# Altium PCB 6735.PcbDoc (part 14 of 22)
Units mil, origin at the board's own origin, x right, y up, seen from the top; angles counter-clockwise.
Board outline 2641.73 x 5165.35 mil, 6 copper layers (Top, Inner Layer 2, Inner Layer 3, Inner Layer 4, Inner Layer 5, Bottom), stack 35.7 mil thick; 1011 components, 790 nets, 4118 pads, 9325 vias.
Unrouted connection lines stored in the file: 4610.
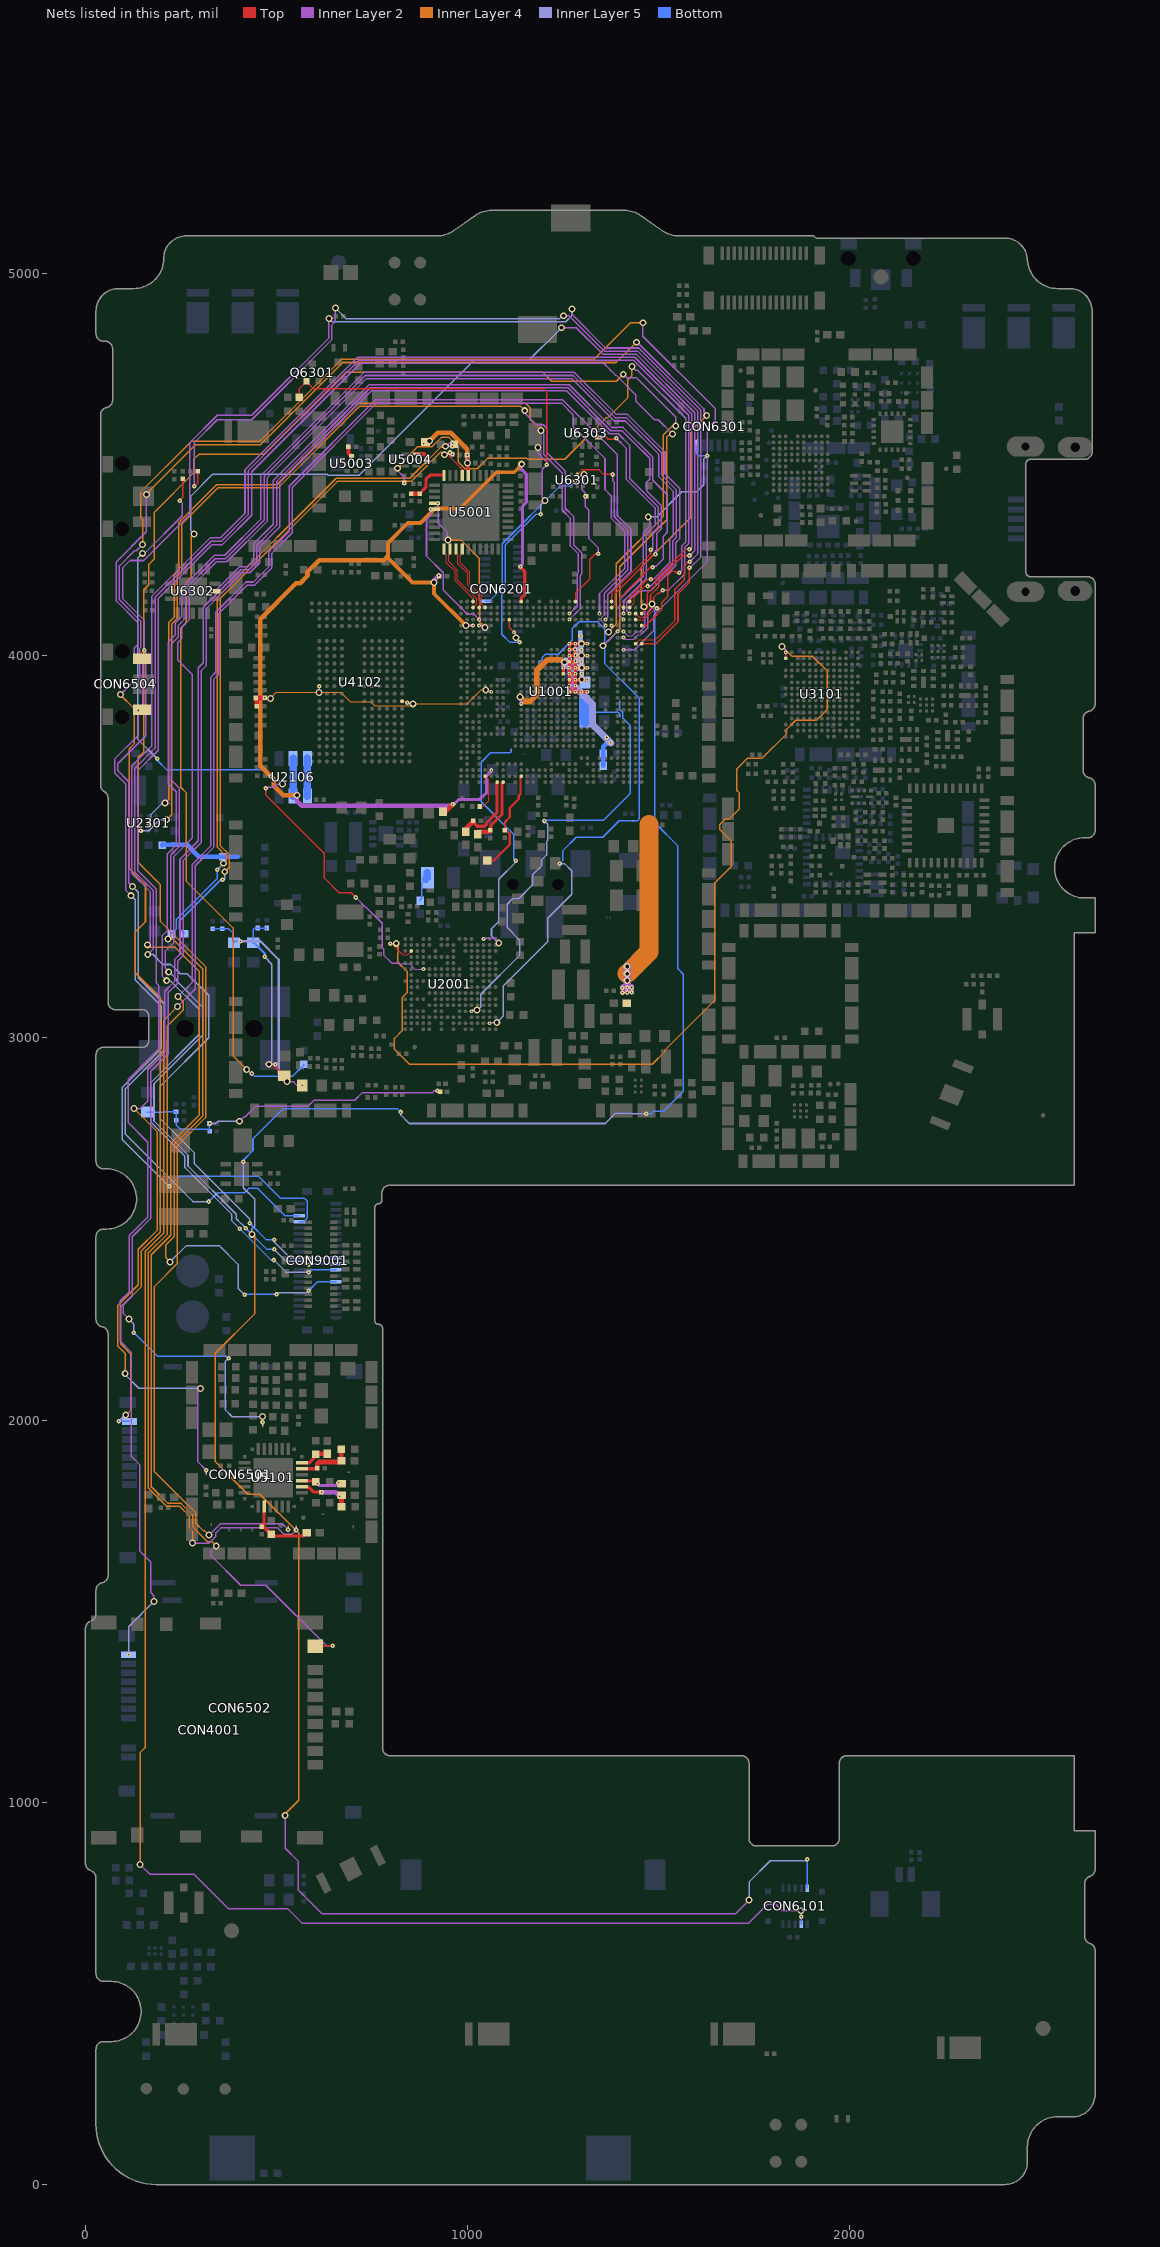
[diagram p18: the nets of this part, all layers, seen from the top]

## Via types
v1: diameter 12, hole 4, Top to Inner Layer 2, 3329 vias
v2: diameter 12, hole 4, Inner Layer 5 to Bottom, 3071 vias
v3: diameter 18, hole 10, Inner Layer 2 to Inner Layer 5, 1928 vias
v4: diameter 10, hole 4, Top to Inner Layer 2, 525 vias
v5: diameter 20, hole 12, Top to Bottom, 472 vias

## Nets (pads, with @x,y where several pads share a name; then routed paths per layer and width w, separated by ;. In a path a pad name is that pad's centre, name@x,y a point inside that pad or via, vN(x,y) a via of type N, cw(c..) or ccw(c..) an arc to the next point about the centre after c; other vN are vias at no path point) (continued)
DVDD18_MSDC0: C10092.1 R1014.1 U1001.C27 U1001.F3 U1001.L31 | length 2756.4
  Top w4: v1(923.95,4209.83) C10092.1@925.95,4207.83 ; U1001.F3@1061.3,3700.59 v4(1061.47,3700.77) 1061.3,3700.76 U1001.F3@1061.3,3700.59
  Top w8: v1(1137.08,4233.11) 1149.31,4220.87 1149.31,4159.09 1140.21,4149.98 U1001.L31@1140.21,4141.71
  Top w12: R1014.1@935.31,3592.09 935.31,3593.09 943.24,3593.09 v1(961.54,3611.4)
  Inner Layer 2 w8: v1(961.54,3611.4) 963.9,3611.15 971.31,3618.57 976.57,3623.83 976.83,3624.09 1031.71,3624.09 1049.8,3642.18 1049.8,3686.34 1061.47,3698.01 v4(1061.47,3700.77) ; v3(995.29,4079.24) 997.95,4078.49 v4(1014.23,4078.72) ; v1(1137.08,4233.11) 1143.31,4239.34 1143.31,4390.93 1153.31,4400.93 1153.31,4475.09 1141.31,4487.09 v3(1141.31,4501.09)
  Inner Layer 2 w12: v3(553.3,3634.73) 553.3,3619.73 565.94,3607.09 957.24,3607.09 v1(961.54,3611.4) ; v3(912.29,4191.35) 912.29,4198.17 v1(923.95,4209.83)
  Inner Layer 4 w10: v3(995.29,4079.24) 912.29,4162.23 v3(912.29,4191.35) 855.63,4191.35 791.31,4255.67 791.31,4260.22 791.31,4295.04 843.34,4347.07 876.94,4347.07 914.97,4385.09 980.73,4385.09 1075.43,4479.79 1121.81,4479.79 1142.21,4500.19 v3(1141.31,4501.09)
  Inner Layer 4 w12: v3(553.3,3634.73) 517.9,3634.73 492.96,3659.68 492.96,3676.39 456.81,3712.53 456.81,4095.59 550.75,4189.53 561.52,4189.53 581.01,4209.02 581.01,4219.64 611.46,4250.09 781.18,4250.09 791.31,4260.22
DVDD28_MSDC1: C10091.1 R1016.1 U1001.G1 | length 211.4
  Top w8: C10091.1@1013.95,3567.83 C10091.1@1014.95,3567.83 ; C10091.1@1014.95,3565.92 1013.04,3565.92 1025.12,3553.83 1044.26,3553.83 1049.31,3558.88 1049.31,3562.14 1077.22,3590.04 U1001.G1@1077.22,3669.27
  Top w12: R1016.1@995.31,3539.09 995.31,3540.09 993.21,3540.09 993.21,3546.09 1013.04,3565.92 C10091.1@1014.95,3567.83 1014.95,3565.92 C10091.1@1014.95,3564.49
DVDD28_SIM1: C10089.1 R1022.1 U1001.H1 | length 188.4
  Top w8: C10089.1@1058.95,3542.83 1060.31,3542.83 1060.31,3552.87 1061.31,3553.87 1061.31,3557.02 1090.31,3586.02 1090.31,3666.61 U1001.H1@1092.97,3669.27
  Top w12: R1022.1@1025.95,3532.49 R1022.1@1025.95,3533.49 ; R1022.1@1029.95,3537.49 R1022.1@1025.95,3533.49 ; C10089.1@1058.95,3542.83 1055.61,3539.49 1025.95,3539.49 R1022.1@1025.95,3533.49
DVDD28_SIM2: C10088.1 R1023.1 U1001.L2 | length 282.6
  Top w6: R1023.1@1051.31,3464.09 1068.09,3464.09 1109.95,3505.95 1109.95,3533.31 1098.19,3545.07 1098.19,3543.83 C10088.1@1097.56,3543.83 ; C10088.1@1096.95,3543.83 C10088.1@1097.56,3543.83 ; U1001.L2@1140.21,3685.02 1137.95,3685.01 1137.95,3638.49 1133.95,3634.49 1133.95,3625.49 1109.95,3601.49 1109.95,3577.49 1097.56,3565.1 C10088.1@1097.56,3543.83
DVDD_EPMU1: C5123.1 R5128.1 SH5102.2 U5101.14 | length 161.6
  Top w4: 668.95,1905.47 669.95,1904.47 SH5102.2@669.95,1893.49
  Top w10: U5101.14@566.2,1872.71 606.3,1872.71 C5123.1@606.3,1874.09
  Top w12: C5123.1@606.3,1874.09 606.3,1886.09 610.7,1890.49 665.95,1890.49 668.95,1893.49 668.95,1905.47 R5128.1@668.95,1923.49
DVDD_EPMU2: C5125.1 R5129.1 SH5105.2 U5101.11 | length 144.6
  Top w4: C5125.1@616.95,1811.49 v1(617.95,1811.49) ; v1(665.31,1801.09) 669.95,1801.09 SH5105.2@670.95,1803.49
  Top w8: U5101.11@566.2,1825.47 583.2,1825.46 596.18,1812.49 616.95,1812.49 C5125.1@616.95,1811.49
  Top w12: R5129.1@669.95,1773.49 SH5105.2@669.95,1801.09
  Inner Layer 2 w12: v1(617.95,1811.49) 654.91,1811.49 v1(665.31,1801.09)
DVDD_IO_NFC: C5121.2 R5116.1 SH5109.2 U5101.3 | length 187.3
  Top w8: C5121.2@460.95,1721.49 467.68,1728.21 U5101.3@467.68,1774.19 ; R5116.1@486.3,1701.09 490.31,1697.08 571.3,1697.08 SH5109.2@579.31,1705.09
  Top w10: C5121.2@460.95,1721.49 465.9,1721.49 R5116.1@486.3,1701.09
DVDD_LTE: C10065.1 C10066.1 C10067.1 C10068.1 C10069.1 C10070.1 C10071.1 C10079.1 C10080.1 R1013.2 SH1004.2 U1001.AA16 U1001.AA18 U1001.AA20 U1001.AA22 U1001.AA24 U1001.AB16 U1001.AB18 U1001.AB20 U1001.AB22 U1001.AB24 U1001.W16 U1001.W17 U1001.W18 U1001.W19 U1001.W20 U1001.W21 U1001.W22 U1001.W23 U1001.W24 U1001.Y16 U1001.Y17 U1001.Y18 U1001.Y19 U1001.Y20 U1001.Y21 U1001.Y22 U1001.Y23 U1001.Y24 | length 1993.7
  Top w4: R1013.2@1416.31,3091.09 1417.31,3091.09 1420.31,3088.09 R1013.2@1421.31,3088.09 ; R1013.2@1417.31,3095.09 R1013.2@1419.54,3096.51
  Top w8: v4(1313.44,3905.49) v4(1297.69,3905.49) v4(1281.94,3905.49) ; v4(1313.44,3936.99) U1001.AA18@1297.69,3936.99 v4(1281.94,3936.99) ; v4(1313.44,3999.98) U1001.AA22@1297.69,3999.98 ; v4(1313.44,4031.47) U1001.AA24@1297.69,4031.47 v4(1281.94,4031.47) ; U1001.W18@1266.2,3936.99 v4(1266.2,3921.24) U1001.W16@1266.2,3905.49 v4(1281.94,3905.49) ; U1001.W18@1266.2,3936.99 v4(1266.2,3952.73) ; U1001.W18@1266.2,3936.99 v4(1281.94,3936.99) ; v4(1266.2,3952.73) v4(1281.94,3952.73) ; v4(1266.2,3952.73) v4(1266.2,3968.48) ; v4(1266.2,3968.48) v4(1281.94,3968.48) ; v4(1266.2,3968.48) U1001.W21@1266.2,3984.23 ; U1001.W21@1266.2,3984.23 v4(1266.2,3999.98) ; U1001.W21@1266.2,3984.23 v4(1266.2,3999.98) ; U1001.W21@1266.2,3984.23 v4(1281.94,3984.23) ; U1001.W21@1266.2,3984.23 v4(1266.2,3999.98) ; U1001.W21@1266.2,3984.23 v4(1281.94,3984.23) ; v4(1266.2,3999.98) v4(1266.2,4015.73) ; v4(1266.2,3999.98) v4(1266.2,4015.73) ; v4(1266.2,3999.98) v4(1281.94,3999.98) ; v4(1266.2,4015.73) v4(1281.94,4015.73) ; v4(1266.2,4015.73) v4(1266.2,4031.47) v4(1281.94,4031.47) ; v4(1281.94,3905.49) v4(1281.94,3921.24) v4(1281.94,3936.99) ; v4(1281.94,3936.99) v4(1281.94,3952.73) ; v4(1281.94,3936.99) v4(1281.94,3952.73) ; v4(1281.94,3952.73) v4(1281.94,3968.48) ; v4(1281.94,3968.48) v4(1281.94,3984.23) ; v4(1281.94,3968.48) v4(1281.94,3984.23) ; v4(1281.94,3968.48) v4(1313.44,3968.48) U1001.AA20@1297.69,3968.48 v4(1281.94,3968.48) ; v4(1281.94,3984.23) v4(1281.94,3999.98) ; v4(1281.94,3999.98) v4(1281.94,4015.73) ; v4(1281.94,3999.98) U1001.AA22@1297.69,3999.98 ; v4(1281.94,3999.98) U1001.AA22@1297.69,3999.98 ; v4(1281.94,4015.73) v4(1281.94,4031.47)
  Top w12: R1013.2@1417.31,3091.09 R1013.2@1417.31,3095.09
  Inner Layer 2 w8: v4(1266.2,3952.73) v4@1281.68,3952.73 ; v4(1266.2,3968.48) v4(1281.94,3968.48) ; v4(1281.94,3936.99) v4@1281.28,3936.56 ; v4(1281.94,3952.73) v4@1281.68,3952.73 ; v3(1297.95,4031.49) 1297.69,4031.47 v4(1313.44,4031.47) ; v3(1298.19,4000.37) 1298.19,4000.17 1313.44,4000.17 v4(1313.44,3999.98) ; v3(1298.24,3968.49) v4(1313.44,3968.48) ; v4(1313.44,3936.99) 1313.44,3937.22 1298.32,3937.22 v3(1298.32,3937.47) v3@1297.69,3936.98 ; v4@1281.28,3936.56 1281.29,3937 1281.31,3937.62 v4@1281.68,3952.73 ; v4@1281.28,3936.56 1281.52,3936.57 1281.96,3936.58 v3@1297.69,3936.98 ; v4@1281.68,3952.74 1282.07,3968.48 1282.08,3969.1 1297.69,3968.48 v3@1297.69,3936.98
  Inner Layer 2 w10: v4(1281.94,3905.49) v4(1266.2,3921.24) ; v4(1281.94,3921.24) v4(1266.2,3921.24) ; v4(1281.94,3984.23) v4(1266.2,3968.48) v4(1266.2,3952.73) 1281.31,3937.62 v4(1281.94,3936.99) 1281.52,3936.57 v4(1266.2,3921.24) ; v4(1297.69,3905.49) v4(1313.44,3905.49)
  Inner Layer 2 w12: v1(1404.8,3131.2) v1@1404.94,3132.15 ; v1(1405.01,3118.63) 1405.21,3120.13 1405.28,3120.27 v1@1405.31,3123.09 ; v1(1429.81,3119.17) 1429.47,3119.65 v1@1429.31,3123.09 ; v1@1404.94,3132.15 1405.31,3135.09 1417.24,3135.09 v1(1417.24,3131.81) 1417.31,3135.09 1429.31,3135.09 v1(1429.67,3131.88) 1429.31,3131.88 v1@1429.31,3123.09 ; v1@1404.94,3132.15 1405.31,3132.15 v1@1405.31,3123.09 ; v1@1405.31,3123.09 v1@1429.31,3123.09
  Inner Layer 2 w20: v1@1417.31,3135.09 v3(1417.31,3150.09) v3(1417.31,3168.09) v3(1417.31,3187.09)
  Inner Layer 4 w20: v3(1417.31,3150.09) v3(1417.31,3168.09)
  Inner Layer 4 w50: v3(1417.31,3168.09) 1474.31,3225.09 1474.31,3238.38 1473.95,3238.74 1473.95,3557.67
  Inner Layer 5 w12: v2(1295.31,4052.09) 1295.31,4034.12 v3(1297.95,4031.49) ; v2(1296.95,4015.49) v2@1297.45,4015.49 ; v2@1298.1,3984.49 1298.1,3968.49 v3(1298.24,3968.49) 1298.6,3968.49 v2@1298.6,3952.49 ; v3(1298.32,3937.47) 1298.64,3937.47 1298.64,3952.49 v2(1298.95,3952.49) ; v2@1282.95,4000.49 v2(1282.95,3988.49) 1282.95,3986.49 1296.95,3986.49 v2(1296.95,3984.49) 1298.07,3984.49 v3@1298.07,4000.37 ; v2@1282.95,4000.49 v2(1282.95,4002.49) ; v2@1282.95,4000.49 v3@1297.57,4000.49 ; v2(1282.95,4002.49) 1282.95,4014.27 v2(1280.79,4016.42) v2@1297.45,4016.42 ; v2(1282.95,4002.49) v3@1297.57,4002.49 ; v2@1297.45,4015.49 1297.57,4015.49 v3@1297.57,4002.49 ; v2@1297.45,4015.49 v2@1297.45,4016.42 ; v2@1297.45,4016.42 v3@1297.45,4026.09 ; v3@1297.45,4026.09 1297.95,4026.09 v3(1297.95,4031.49) ; v3@1297.45,4026.09 1297.45,4031.49 v3(1297.95,4031.49) ; v3@1297.57,4000.49 v3@1297.57,4002.49 ; v3@1297.57,4000.49 v3@1298.15,4000.49 ; v3@1297.57,4000.49 v3(1298.19,4000.37) ; v3@1297.57,4000.49 1297.57,4000.37 v3@1298.07,4000.37 ; v3@1297.57,4002.49 v3@1298.16,4000.49 ; v3@1297.57,4002.49 1298.19,4002.49 1298.19,4000.49 v3(1298.19,4000.37) ; v3@1298.07,4000.37 v3(1298.19,4000.37) ; v3@1298.15,4000.49 v3(1298.19,4000.37) ; v3@1298.16,4000.49 v3(1298.19,4000.37)
  Bottom w4: C10069.1@1294.95,4059.49 1295.31,4059.12 v2(1295.31,4052.09) ; C10067.1@1301.31,3828.49 C10067.1@1306.36,3828.49 C10067.1@1306.36,3826.49 ; 1312.9,3852.16 1393.47,3852.16 1397.31,3848.32 SH1004.2@1397.31,3842.09
  Bottom w12: C10071.1@1294.95,4016.49 C10070.1@1294.95,4037.49
  Bottom w30: C10067.1@1306.36,3828.49 C10066.1@1306.36,3879.49
  other v1: 1417.17,3118.83
DVDD_SIM1: C5124.1 SH5101.2 U5101.15 | length 82.7
  Top w8: U5101.15@566.2,1888.46 585.85,1888.46 605.42,1908.02 C5124.1@605.42,1910.49
  Top w12: C5124.1@605.42,1910.49 C5124.1@602.95,1910.49 603.95,1911.49 SH5101.2@632.95,1911.49
DVDD_SIM2: C5126.1 SH5104.2 U5101.12 | length 117.9
  Top w4: C5126.1@602.95,1838.49 v1(607.31,1834.09) ; v1(662.11,1836.06) 670.95,1836.06 SH5104.2@670.95,1833.49
  Top w8: U5101.12@566.2,1841.22 566.2,1841.49 U5101.12@566.2,1841.22 602.95,1841.21 C5126.1@602.95,1838.49
  Inner Layer 2 w8: v1(607.31,1834.09) 612.84,1828.56 654.61,1828.56 v1(662.11,1836.06)
DVDD_SRAM: C10004.1 C10005.1 R1027.1 U1001.L14 U1001.V19 U1001.V20 | length 616.7
  Top w8: U1001.V19@1250.45,3952.73 1250.45,3968.41 v4(1250.45,3968.48)
  Inner Layer 2 w10: v3(1136.82,3891.87) 1140.21,3888.47 v4(1140.21,3873.99)
  Inner Layer 2 w12: v4@1250.45,3968.48 1250.45,3982.83 v3(1252.95,3982.83)
  Inner Layer 4 w15: v3(1136.82,3891.87) 1148.48,3880.2 1163.01,3880.2 1180.95,3898.14 1180.95,3961.84 1208.66,3989.55 1244.56,3989.55 1252.09,3982.02 v3(1252.95,3982.83)
  Inner Layer 5 w4: v2@1373.82,3772.6 1374.31,3773.09 1375.31,3773.09 v2(1374.56,3771.86)
  Inner Layer 5 w18: v3(1252.95,3982.83) 1252.76,3982.68 1277.21,3958.23 1277.21,3923.49 1326.95,3873.75 1326.95,3819.47 1373.82,3772.6 v2(1374.56,3771.86)
  Bottom w4: C10005.1@1374.31,3772.09 v2(1374.56,3771.86)
  Bottom w12: R1027.1@1354.31,3712.09 C10004.1@1354.31,3745.09 1354.31,3761.43 1363.97,3771.09 1374.31,3771.09 1374.05,3771.35 v2(1374.56,3771.86) ; v2(1363.38,3785.95) 1374.31,3775.01 C10005.1@1374.31,3772.09
EINT_ACC: U1001.AH29 U6303.5 | length 584.7
  Top w4: U6303.5@1341.94,4571.65 1362.79,4571.64 1367.95,4566.49 1386.67,4566.49 v1(1388.93,4568.75)
  Inner Layer 2 w4: v1(1388.93,4568.75) 1415.46,4542.22 1415.46,4461.32 1490.31,4386.46 1490.31,4340.4 1467.31,4317.4 1467.31,4202.09 1407.93,4142.71 v4(1407.93,4110.21)
EINT_ALPS: CON6301.1 U1001.AH28 | length 621
  Inner Layer 2 w3: 1402.67,4151.09 1397.42,4145.84 1397.42,4104.97 v4(1407.93,4094.47)
  Inner Layer 2 w4: 1402.67,4151.09 1459.31,4207.73 1459.31,4320.72 1476.31,4337.72 1476.31,4359.28 v3(1472.5,4363.1)
  Inner Layer 5 w4: v3(1472.5,4363.1) 1494.66,4363.1 1560.31,4428.75 1598.84,4428.75 1617.42,4447.33 1617.42,4514.62 1626.34,4523.54 v2(1627.09,4522.8)
  Bottom w4: CON6301.1@1597.87,4550.11 1597.87,4528.95 1604.03,4522.8 v2(1627.09,4522.8)
EINT_CTP: CON6101.9 U1001.AH25 | length 6387
  Top w4: v4(1407.93,4047.22) 1407.93,4047.7 v4(1407.93,4047.22)
  Inner Layer 2 w3: v4(1407.93,4047.22) 1412.04,4043.11 1434.08,4043.11 1445.46,4054.49 1453.23,4054.49 1457.23,4058.49
  Inner Layer 2 w4: v3(522.55,965.62) 522.55,879.86 556.13,846.27 556.13,771.09 618.13,709.09 1701.31,709.09 v3(1736.31,744.09) ; 1457.23,4058.49 1471.31,4072.57 1471.31,4113.67 1481.52,4123.87 1481.52,4134.87 v3(1482.62,4134.87)
  Inner Layer 4 w4: v3(435.31,2486.09) 442.31,2479.09 442.31,2277.83 339.31,2174.83 339.31,1891.56 424.78,1806.09 456.26,1806.09 557.95,1704.4 557.95,1005.35 521.58,968.98 521.58,959.08 v3(522.55,965.62)
  Inner Layer 5 w4: v2(412.95,2676.32) 412.95,2607.95 443.31,2577.59 443.31,2508.09 435.31,2500.09 v3(435.31,2486.09) ; v2(825.31,2806.09) 825.31,2798.09 847.31,2776.09 1360.21,2776.09 1386.95,2802.83 1426.2,2802.83 1427.88,2801.15 v2(1467.12,2801.15) ; v3(1482.62,4134.87) 1483.08,4135.33 1494.82,4123.59 v2(1495.28,4124.05) ; v3(1736.31,744.09) 1736.31,791.49 1791.91,847.09 1887.95,847.09 1887.95,851.39 v2(1888,851.44)
  Bottom w4: v2(412.95,2676.32) 414.15,2681.09 438.31,2705.25 438.31,2736.09 516.31,2814.09 817.31,2814.09 v2(825.31,2806.09) ; v2(1467.12,2801.15) 1478.73,2801.15 1485.15,2807.57 1511.8,2807.57 1564.31,2860.09 1564.31,3166.69 1550,3181 1550,3502.16 1489.31,3562.85 1489.31,4118.08 v2(1495.28,4124.05) ; CON6101.9@1888,775.18 v2(1888,851.44)
EINT_EAR: R6005.2 U1001.AK29 | length 3981.9
  Top w3: U1001.AK29@1439.43,4110.21 1448.84,4100.79 1459.07,4100.79 1478.31,4120.03 1478.31,4143.86
  Top w4: 1478.31,4143.86 1478.31,4158.49 1499.83,4180.01 1499.83,4197.59 1564.33,4262.09 v1(1580.31,4262.09)
  Inner Layer 2 w4: v3(1245.37,4858.16) 1284.31,4858.16 1353.39,4789.09 1440.73,4789.09 1594.31,4635.51 1594.31,4275.12 1580.8,4261.6 v1(1580.31,4262.09)
  Inner Layer 4 w4: v3(283.95,4318.83) 276.63,4311.51 276.63,4205.29 264.31,4192.97 264.31,4087.09 249.31,4072.09 249.31,3655.78 264.31,3640.78 264.31,3409.58 386.31,3287.58 386.31,2953.1 v3(421.82,2917.59)
  Inner Layer 5 w4: v3(283.95,4318.83) 275.95,4326.83 275.95,4418.06 333.03,4475.14 631.31,4475.14 634.36,4472.09 715.92,4472.09 1017.92,4774.09 1161.21,4774.09 1232.95,4845.83 v3(1245.37,4858.16) ; v3(421.82,2917.59) 422.52,2918.29 434.59,2906.22 v2(435.29,2906.92)
  Bottom w4: v2(435.29,2906.92) 442.12,2900.09 542.53,2900.09 570.95,2928.51 R6005.2@570.95,2931.49
EINT_GYRO: U1001.AH30 U6302.7 | length 2028.1
  Top w3: U1001.AH30@1407.93,4125.96 1403.56,4130.33 1399.18,4134.7 1398.31,4135.57 1398.31,4151.81 1405.39,4158.88 1406.11,4158.88 1412.31,4165.09
  Top w4: v1(331.88,4168.49) 331.92,4169.2 331.95,4169.83 338.02,4169.83 U6302.7@339.02,4168.83 ; 1412.31,4165.09 1478.42,4231.2 v1(1483.98,4231.2)
  Inner Layer 2 w4: v1(331.88,4168.49) 338.8,4168.49 403.14,4232.83 422.92,4232.83 439.95,4249.86 439.95,4292.63 491.31,4343.99 491.31,4458.48 741.92,4709.09 1265.6,4709.09 1377.6,4597.09 1392.31,4597.09 1392.59,4597.37 1406.63,4597.37 1484.31,4519.69 1484.31,4459.29 1522.31,4421.29 1522.31,4322.8 1512.31,4312.8 1512.31,4253.42 1493.34,4234.45 1487.23,4234.45 v1(1483.98,4231.2)
EINT_M: U1001.AE27 U6301.C2 | length 548.5
  Top w4: v1(1379.31,4474.18) 1355.69,4474.18 1343.79,4486.09 1298.8,4486.09 U6301.C2@1286.96,4474.24 ; U6301.C2@1286.95,4474.24 1287.45,4474.23 U6301.C2@1286.96,4474.24
  Inner Layer 2 w3: 1357.08,4106.61 1350.81,4100.34 1350.81,4090.44 1361.61,4079.64 v4(1360.69,4078.72)
  Inner Layer 2 w4: 1357.08,4106.61 1357.08,4162.86 1419.31,4225.09 1419.31,4327.72 1383.31,4363.72 1383.31,4454.19 1379.31,4458.19 v1(1379.31,4474.18)
EINT_NFC: SH5112.1 U1001.AE28 | length 4808.5
  Top w4: v1@550.95,1711.49 v1(550.95,1712.49) SH5112.1@550.95,1719.49 ; v4(1360.69,4094.47) 1361.31,4095.09 v4(1360.69,4094.47)
  Inner Layer 2 w4: v3(242.31,3108.09) 279.31,3145.09 279.31,3453.85 327.31,3501.85 327.31,3943.24 340.82,3956.75 340.82,4113.81 419.84,4192.83 439.49,4192.83 479.95,4233.29 479.95,4272.51 532.95,4325.51 532.95,4443.55 758.49,4669.09 1248.91,4669.09 1391.31,4526.68 1391.31,4367.03 1427.31,4331.03 1427.31,4221.09 1366.31,4160.09 1366.31,4100.09 v4(1360.69,4094.47) ; v3(280.31,1678.09) 323.53,1678.09 340.31,1694.88 340.31,1703.75 354.65,1718.09 502.9,1718.09 519.9,1701.09 539.55,1701.09 v1(550.95,1712.49)
  Inner Layer 4 w4: v3(242.31,3108.09) 255.95,3094.45 255.95,3073.36 214.31,3031.72 214.31,2486.91 164.31,2436.91 164.31,1822.5 212.73,1774.09 246.94,1774.09 271.9,1749.13 271.9,1718.09 280.31,1709.68 v3(280.31,1678.09)
EINT_SD: CON4001.12 U1001.AL29 | length 5655.1
  Top w4: CON4001.12@601.19,1408.54 628.45,1408.54 629.01,1409.09 v1@647.91,1409.09 ; v1(646.95,1409.49) 647.51,1409.49 v1@647.91,1409.09 ; v1@649.58,1409.09 v1@647.91,1409.09 ; U1001.AL29@1455.17,4110.21 1470.31,4125.35 1470.31,4163.32 1491.6,4184.61 1491.6,4200.67 1569.02,4278.09 v1(1580.31,4278.09)
  Inner Layer 2 w4: v3(162.21,3243.55) 169.09,3250.42 169.09,3382.8 121.31,3430.58 121.31,3711.72 173.92,3764.32 173.92,4155.9 327.16,4309.15 353.94,4309.15 417.4,4372.6 417.4,4486.4 712.1,4781.09 1437.42,4781.09 1586.31,4632.19 1586.31,4282.09 1582.31,4278.09 v1(1580.31,4278.09) ; v3(342.04,1670.79) 327.31,1656.06 327.31,1647.12 406.34,1568.09 471.97,1568.09 630.57,1409.49 v1(646.95,1409.49)
  Inner Layer 4 w4: v3(162.21,3243.55) 168.67,3237.09 234.27,3237.09 298.31,3173.04 298.31,2799.09 223.31,2724.09 223.31,2483.87 172.31,2432.87 172.31,1825.82 216.04,1782.09 250.25,1782.09 280.31,1752.03 280.31,1720.99 298.31,1702.99 298.31,1702.88 319.86,1681.33 331.5,1681.33 v3(342.04,1670.79)
ENBB_6169: U2001.R3 U3101.N1 U3101.N2 | length 2577.5
  Top w3: v1(797.26,3246.47) 801.89,3246.47 830.33,3218.02 843.17,3218.02 848.23,3223.09 ; 844.97,3219.83 848.23,3223.09 ; U2001.R3@852.59,3227.44 848.23,3223.09
  Top w4: v1@797.11,3246.47 v1(797.26,3246.47) ; U3101.N2@1832.16,3993.08 v4(1832.16,4008.83)
  Inner Layer 2 w4: v1(797.26,3246.47) 798.32,3245.4 798.39,3245.47 810.94,3245.47 812.96,3247.5 v3(813.25,3247.5) ; v3(1822.65,4024.29) 1823.18,4024.81 1832.16,4015.83 v4(1832.16,4008.83)
  Inner Layer 4 w4: v3(813.25,3247.5) 818.31,3242.44 818.31,3222.14 817.31,3221.14 817.31,3197.96 841.31,3173.96 841.31,3118.09 828.31,3105.09 828.31,3018.68 808.31,2998.68 808.31,2970.25 847.47,2931.09 1482.79,2931.09 1516.31,2964.62 1516.31,2968.27 1645.95,3097.91 ; 1645.95,3097.06 1645.95,3097.91 ; v3(1822.65,4024.29) 1848.29,3998.65 1901.69,3998.65 1940.65,3959.69 1940.65,3891.44 1940.79,3891.3 1940.79,3878.88 1940.65,3878.74 1940.65,3873.04 1941.11,3872.58 1941.11,3860.16 1940.65,3859.7 1940.65,3859.38 1912.32,3831.04 1858.58,3831.04 1834.13,3806.6 1834.13,3795.28 1770.95,3732.1 1732.88,3732.1 1704.06,3703.28 1704.06,3647.74 1711.08,3640.73 1711.08,3599.83 1682.78,3571.54 1672.88,3571.54 1659.65,3558.31 1659.65,3545.26 1689.05,3515.86 1689.05,3447.54 1645.95,3404.44 1645.95,3097.91
EVREF: C4115.1 C4116.1 R1103.1 U1001.F16 U4102.M2 U4102.P13 | length 729.9
  Top w3: U4102.P13@828.35,3880.9 838.29,3880.89 v1(842.08,3877.11)
  Top w12: C4116.1@445.31,3889.39 C4116.1@449.09,3889.39 ; R1103.1@447.95,3867.49 447.95,3888.25 C4116.1@449.09,3889.39 ; C4115.1@468.95,3889.49 468.85,3889.39 C4116.1@449.09,3889.39
  Inner Layer 2 w3: v3(611.08,3904.11) 611.08,3920.26 v1(611.81,3920.26) ; v1(842.08,3877.11) 854.08,3877.11 v3(857.08,3874.11) ; v3(1047.3,3910.55) 1052.37,3905.48 v4(1061.47,3905.49)
  Inner Layer 2 w4: v1(468.81,3890.33) 468.81,3889.33 483.81,3889.33 v3(483.81,3888.33)
  Inner Layer 4 w3: v3(483.81,3888.33) 499.59,3904.11 v3(611.08,3904.11) 667.73,3904.11 692.78,3879.06 746.13,3879.06 756.61,3868.58 851.55,3868.58 v3(857.08,3874.11) 998.81,3874.11 1035.26,3910.55 v3(1047.3,3910.55)
EXTDN: R1101.1 U1001.E2 | length 100.1
  Top w3: R1101.1@1032.89,3604.55 1031.95,3604.55 R1101.1@1031.95,3605.49 1040.59,3605.49 1055.3,3620.2 1055.3,3675.44 U1001.E2@1045.72,3685.02
F2W_CLK: U1001.D28 U5001.5 | length 386
  Top w4: U5001.5@903.17,4382.98 U5001.5@908.95,4382.98 ; v1(903.31,4383.14) 908.79,4383.14 U5001.5@908.95,4382.98 ; U5001.5@923.08,4383.11 U5001.5@913.14,4383.11 ; U5001.5@908.95,4382.98 U5001.5@913.02,4382.98 ; U5001.5@913.02,4382.98 U5001.5@913.14,4383.11 ; U5001.5@913.02,4382.98 U5001.5@913.14,4383.11
  Inner Layer 2 w4: v1(903.31,4383.14) 903.31,4366.92 892.31,4355.92 892.31,4260.83 935.95,4217.19 935.95,4171.67 998.79,4108.83 1015.61,4108.83 v4(1029.98,4094.47)
F2W_DATA: U1001.D27 U5001.4 | length 423.2
  Top w4: U5001.4@913.02,4398.73 921.31,4398.73 v1(921.31,4399.09)
  Inner Layer 2 w4: v1@921.06,4398.83 v1(921.31,4399.09) 923.31,4397.09 923.31,4346.24 947.12,4322.43 947.12,4302.55 v3(948.15,4302.55) ; v4(1029.98,4078.72) 1040.69,4078.71 v3(1045.31,4074.09)
  Inner Layer 4 w4: v3(948.15,4302.55) 982.23,4302.55 1030.31,4254.46 1030.31,4144.77 1031.31,4143.77 1031.31,4088.09 v3(1045.31,4074.09)
FLASH_1: C2323.1 LED2302.1 R2320.2 | length 212.2
  Bottom w12: R2320.2@200.95,3503.49 R2320.2@200.95,3504.49 200.95,3505.49 C2323.1@229.95,3505.49 265.87,3505.49 296.88,3474.48 LED2302.1@358.89,3473.5 398.3,3474.48
FM_ANT: L5002.1 L6001.2 R5013.1 | length 1762.7
  Top w4: v1(961.44,4555.73) 962.9,4552.12 963.31,4551.09 L5002.1@965.31,4553.09
  Inner Layer 2 w4: v3(941.89,4547.87) 942.36,4547.4 951.05,4556.09 961.08,4556.09 v1(961.44,4555.73)
  Inner Layer 4 w4: v3(360.95,3456.83) 367.95,3463.83 367.95,3476.28 344.31,3499.92 344.31,4152.54 655.86,4464.09 848.31,4464.09 930.31,4546.09 938.12,4546.09 940.9,4548.87 v3(941.89,4547.87)
  Inner Layer 5 w4: v2(345.26,3439.75) 344.92,3440.1 361.3,3456.48 v3(360.95,3456.83) ; v3(941.89,4547.87) 941.89,4547.69 960.06,4547.69 v2(960.06,4547.5)
  Bottom w4: L6001.2@224.95,3271.49 224.95,3272.49 237.31,3284.85 237.31,3309.55 345.26,3417.5 v2(345.26,3439.75)
FM_AVDD28: BEAD5001.1 C5008.2 U5001.36 | length 268.5
  Top w4: v1(884.87,4555.09) 889.31,4555.09 BEAD5001.1@889.31,4559.09 ; C5008.2@998.31,4525.09 C5008.2@998.31,4524.09 v1(999.31,4525.09)
  Top w8: C5008.2@998.31,4524.09 1001.21,4521.2 U5001.36@1001.21,4471.17 ; U5001.36@1001.21,4471.17 1000.96,4471.17 U5001.36@1001.21,4471.17
  Inner Layer 2 w12: v1(884.87,4555.09) 895.51,4555.09 901.39,4560.97 v3(900.28,4562.09) ; v3(999.31,4504.09) v1(999.31,4525.09)
  Inner Layer 4 w12: v3(900.28,4562.09) 921.28,4583.09 956.17,4583.09 999.31,4539.95 v3(999.31,4504.09)
FM_RX_N_6625: R5006.1 R6012.2 U5001.37 | length 1817.4
  Top w4: v1(953.76,4531.6) 953.76,4519.67 970.88,4502.55 985.46,4487.97 U5001.37@985.46,4471.17
  Inner Layer 2 w4: v3(939.39,4525.91) 939.57,4526.09 948.25,4526.09 v1(953.76,4531.6)
  Inner Layer 4 w4: v3(364.31,3434.83) 375.95,3446.47 375.95,3479.59 352.31,3503.23 352.31,4149.23 659.17,4456.09 852.64,4456.09 928.64,4532.09 939.39,4532.09 v3(939.39,4525.91)
  Inner Layer 5 w4: v2(358.65,3413.9) 364.63,3413.83 364.63,3434.83 v3(364.31,3434.83) ; v3(939.39,4525.91) 939.39,4526.71 960.06,4526.71 v2(960.06,4527.5)
  Bottom w4: R6012.2@258.95,3272.49 245.31,3286.13 245.31,3305.05 354.09,3413.83 358.65,3413.83 v2(358.65,3413.9)
GND_VCORE_FB: SH1005.2 U2001.C1 | length 685.4
  Inner Layer 2 w4: v4(1041.57,3258.94) 1043.71,3261.09 1068.25,3261.09 v3(1081.25,3248.09)
  Inner Layer 5 w4: v3(1081.25,3248.09) 1062.31,3267.03 1062.31,3285.88 1081.31,3304.88 1081.31,3414.83 1125.47,3458.99 v2(1125.47,3463.9)
  Bottom w4: SH1005.2@1113.95,3753.49 1113.95,3748.67 1110.77,3745.49 1059.32,3745.49 1035.31,3721.48 1035.31,3617.71 1120.64,3532.38 1120.64,3468.73 v2(1125.47,3463.9)
GND_VLTE_FB: SH1003.2 U2001.E13 | length 1134.9
  Inner Layer 2 w4: v4(1010.07,3069.96) 1012.62,3072.51 1024.82,3072.51 v3(1024.82,3072.76)
  Inner Layer 5 w4: v3(1024.82,3072.76) 1025.6,3072.51 1034.31,3081.22 1034.31,3114.2 1135.95,3215.84 1135.95,3256.09 1103.31,3288.73 1103.31,3349.93 1117.37,3363.99 1133.4,3363.99 1169.95,3400.55 1169.95,3427.03 1194.33,3451.41 1194.33,3466.57 1206.31,3478.55 1206.31,3513.63 1209.31,3516.63 1209.31,3559.06 v2(1200.77,3567.6)
  Bottom w4: v2(1200.77,3567.6) 1202.31,3570.09 1355.94,3570.09 1425.31,3639.46 1425.31,3817.69 1405.33,3837.67 1405.33,3851.81 1397.31,3859.83 SH1003.2@1397.31,3880.09
GND_VPROC_PMIC_FB: R1037.1 SH1002.1 | length 805.4
  Bottom w4: SH1002.1@1186.31,3973.09 1186.31,3981.09 1195.02,3989.8 1195.02,3995.28 1203.83,4004.09 1237.13,4004.09 1273.31,4040.27 1273.31,4070.21 1292.19,4089.09 1339.74,4089.09 1358.31,4070.52 1358.31,3979.68 1449.31,3888.68 1449.31,3573.09 1444.31,3568.09 R1037.1@1434.31,3568.09
GND_VPROC_PMIC_FB_6328: R1037.2 U2001.B15 | length 788.3
  Inner Layer 2 w4: v4(1057.32,3038.47) 1057.31,3039.27 1076.31,3039.27 v3(1076.31,3040.08)
  Inner Layer 5 w4: v3(1076.31,3040.08) 1093.31,3057.08 1093.31,3136.09 1209.31,3252.09 1209.31,3313.09 1272.31,3376.09 1272.31,3437.09 1253.31,3456.09 v2(1241.31,3456.09)
  Bottom w4: v2(1241.31,3456.09) 1249.31,3464.09 1249.31,3490.16 1284.24,3525.09 1353.31,3525.09 1396.31,3568.09 R1037.2@1430.31,3568.09
GPIO_CAMERA_RESET: CON6201.21 R6211.2 U1001.Y31 | length 854.6
  Top w4: U1001.Y31@1281.94,4141.71 1283.31,4141.71 1283.31,4164.65 1308.75,4190.09 1309.18,4190.09 1318.95,4199.86 1318.95,4251.06 1334.72,4266.83 v1(1341.95,4266.83) ; v1(1307.31,4417.56) 1310.31,4417.56 R6211.2@1310.31,4417.09
  Inner Layer 2 w4: v3(1304.31,4474.09) 1298.31,4474.09 1298.31,4435.09 1307.31,4426.09 v1(1307.31,4417.56) 1307.31,4390.78 1317.31,4380.78 1317.31,4306.52 1341.95,4281.88 v1(1341.95,4266.83)
  Inner Layer 5 w4: v2(1281.31,4457.09) 1298.31,4474.09 v3(1304.31,4474.09)
  Bottom w4: CON6201.21@1046.63,4142.9 1046.63,4141.89 1055.91,4141.89 1090.31,4176.29 1090.31,4292.82 1241.58,4444.09 1268.31,4444.09 v2(1281.31,4457.09)
GPIO_CTP_RSTB: CON6101.8 U1001.AD29 | length 7077.7
  Inner Layer 2 w4: v3(142.95,837.49) 168.66,811.78 283.64,811.78 373.33,722.09 528.38,722.09 566.38,684.09 1735.17,684.09 1784.17,733.09 1805.81,733.09 1822.71,716.19 v3(1872.25,716.19) ; v3(240.95,3081.83) 287.31,3128.19 287.31,3450.49 335.31,3498.49 335.31,3937.86 348.95,3951.5 348.95,4110.63 423.15,4184.83 442.8,4184.83 487.95,4229.98 487.95,4268.48 540.95,4321.48 540.95,4440.24 761.8,4661.09 1245.27,4661.09 1276.31,4630.04 1276.31,4599.25 1359.31,4516.25 1359.31,4434.51 1375.31,4418.51 1375.31,4360.4 1411.31,4324.4 1411.31,4229.09 1344.93,4162.71 v4(1344.94,4110.21)
  Inner Layer 4 w4: v3(142.95,837.49) 142.95,1130.37 156.31,1143.73 156.31,2441 205.31,2490 205.31,3046.19 v3(240.95,3081.83)
  Inner Layer 5 w4: v2(1872.25,700.19) v3(1872.25,716.19)
  Bottom w4: CON6101.8@1872.25,680.7 v2(1872.25,700.19)
GPIO_FLASH_EN: U1001.W28 U2301.C1 | length 2531.4
  Inner Layer 2 w3: v4(1266.2,4094.47) 1280.22,4108.49
  Inner Layer 2 w4: v3(1149.31,4641.09) 1149.31,4635.09 1179.86,4604.54 1197.47,4604.54 1207.19,4594.81 1207.19,4531.62 1255.31,4483.5 1255.31,4385.59 1276.95,4363.95 1276.95,4290.24 1297.89,4269.3 1297.89,4213.62 1294.95,4210.68 1294.95,4123.22 1280.22,4108.49
  Inner Layer 4 w4: v3(212.3,3570.8) 225.31,3583.81 225.31,4082.4 240.31,4097.4 240.31,4206.94 252.31,4218.94 252.31,4345.03 346.37,4439.09 503.68,4439.09 717.68,4653.09 1137.31,4653.09 v3(1149.31,4641.09)
  Inner Layer 5 w4: v2(145.26,3541.82) 165.3,3541.82 194.57,3571.09 212.3,3571.09 v3(212.3,3570.8)
GPIO_FLASH_STROBE: U1001.W29 U2301.B2 | length 2478.7
  Inner Layer 2 w4: v3(1191.54,4589.26) 1191.15,4588.87 1199.07,4580.95 1199.07,4526.39 1247.31,4478.15 1247.31,4380.57 1268.95,4358.93 1268.95,4286.91 1289.89,4265.97 1289.89,4217.81 1286.95,4214.87 1286.95,4130.97 v4(1266.2,4110.21)
  Inner Layer 4 w4: v3(208.31,3614.52) 217.31,3623.52 217.31,4085.96 232.31,4100.96 232.31,4211.26 244.31,4223.26 244.31,4348.34 343.06,4447.09 500.36,4447.09 714.36,4661.09 1150.53,4661.09 1164.31,4647.3 1164.31,4616.48 v3(1191.54,4589.26)
  Inner Layer 5 w4: v2(164.95,3561.49) 171.31,3567.85 171.31,3584.83 201.23,3614.74 208.09,3614.74 v3(208.31,3614.52)
GPIO_GPS_LNA_EN: R5015.2 U1001.AL27 | length 1724.9
  Top w4: R5015.2@834.08,4452.11 834.08,4451.11 834.1,4451.2 v1(834.21,4451.18) ; U1001.AL27@1455.17,4078.72 1466.26,4078.71 1484.31,4096.77 1508.31,4120.77 1508.31,4139.83 1523.31,4154.83 1523.31,4209.76 1534.06,4220.51 1541.57,4220.51 1544.97,4217.11 v1(1553.97,4217.11)
  Inner Layer 2 w4: v3(816.61,4490.49) 816.8,4490.49 816.78,4487.3 815.2,4485.72 834.21,4466.71 v1(834.21,4451.18) ; v3(1429.55,4756.43) 1438.89,4747.09 1444.46,4747.09 1570.31,4621.24 1570.31,4297.3 1560.31,4287.3 1560.31,4223.81 1553.79,4217.29 v1(1553.97,4217.11)
  Inner Layer 4 w4: v3(816.61,4490.49) 816.66,4490.49 816.2,4487.88 823.98,4495.65 823.98,4501.97 868.1,4546.09 906.2,4546.09 931.2,4571.09 951.2,4571.09 975.31,4546.98 975.31,4506.88 993.1,4489.09 1024.79,4489.09 1051.79,4516.09 1154.87,4516.09 1156.87,4514.09 1253.84,4514.09 1361.84,4622.09 1366.02,4622.09 1418.31,4674.39 1418.31,4720.4 1429.55,4731.64 v3(1429.55,4756.43)
GPIO_NFC_ENB: SH5115.1 U1001.AF31 | length 4526.2
  Top w4: SH5115.1@463.31,1986.09 v1(463.31,1994.09) ; U1001.AF31@1376.43,4141.71 1376.43,4164.09 1478.33,4265.99 1478.33,4275.96 v1(1479.44,4277.06)
  Inner Layer 2 w4: v3(113.7,2264.36) 99.31,2278.75 99.31,2302.12 122.31,2325.12 122.31,2479.62 171.31,2528.62 171.31,2912.78 216.12,2957.58 216.12,3118.03 241.31,3143.22 241.31,3200.92 255.31,3214.92 255.31,3464.09 303.31,3512.09 303.31,3961.26 316.42,3974.37 316.42,4123.35 409.9,4216.83 429.55,4216.83 455.95,4243.24 455.95,4284.59 508.29,4336.92 508.29,4452.83 748.55,4693.09 1258.89,4693.09 1371.22,4580.76 1393.89,4580.76 1423.55,4551.1 1423.55,4464.54 1498.31,4389.78 1498.31,4336.03 1483.95,4321.67 1483.95,4277.06 v1(1479.44,4277.06) ; v1(463.31,1994.09) 462.31,1995.09 462.31,2008.09 v3(463.31,2009.09)
  Inner Layer 5 w4: v3(113.7,2264.36) 126.31,2251.75 v2(126.31,2229.09) ; v2(374.5,2161.63) 365.31,2152.45 365.31,2027.56 383.78,2009.09 v3(463.31,2009.09)
  Bottom w4: v2(126.31,2229.09) 188.31,2167.09 368.31,2167.09 v2(374.5,2161.63)
GPIO_NFC_IRQ: SH5113.1 U1001.AF27 | length 5375.7
  Top w4: v1(529.95,1713.49) 530.95,1714.53 SH5113.1@530.95,1719.49
  Inner Layer 2 w4: v3(323.31,1699.09) 333.02,1708.79 353.06,1728.83 514.61,1728.83 v1(529.95,1713.49) ; v3(1368.31,4062.09) 1376.43,4070.2 v4(1376.43,4078.72) ; v3(1407.14,4736.41) 1416.46,4727.09 1441.84,4727.09 1544.27,4624.65 v3(1544.27,4600.81)
  Inner Layer 4 w4: v3(323.31,1699.09) 312.42,1709.98 308.76,1709.98 288.31,1730.43 288.31,1756.89 180.31,1864.89 180.31,2349.55 240.31,2409.55 240.31,2717.45 314.31,2791.45 314.31,3186.57 195.31,3305.57 195.31,3401.97 138.31,3458.97 138.31,3734.26 152.31,3748.26 152.31,4172.64 165.31,4185.64 165.31,4238.52 180.31,4253.52 180.31,4375.08 282.95,4477.72 282.95,4513.04 297,4527.09 467.13,4527.09 681.13,4741.09 1196.86,4741.09 1220.12,4717.83 1388.56,4717.83 v3(1407.14,4736.41) ; v3(1368.31,4062.09) 1388.88,4082.66 1388.88,4240.84 1512.31,4364.27 1512.31,4578.14 1534.98,4600.81 v3(1544.27,4600.81)
GPIO_NFC_RSTB: SH5114.1 U1001.AF30 | length 4657.6
  Top w3: U1001.AF30@1376.43,4125.96 1377.42,4125.96 1385.95,4134.49 1385.95,4160.36 1385.09,4161.21
  Top w4: SH5114.1@316.31,1861.09 v1(316.31,1869.09) ; 1385.09,4161.21 1385.09,4161.32 1489.69,4265.92 v1(1491.44,4265.92)
  Inner Layer 2 w4: v3(127.31,2815.09) 143.31,2815.09 162.55,2834.33 162.55,2916.41 207.73,2961.59 207.73,3122.36 233.01,3147.63 233.01,3204.8 247.31,3219.1 247.31,3467.62 295.31,3515.62 295.31,3968.52 308.29,3981.49 308.29,4126.53 406.59,4224.83 426.23,4224.83 447.95,4246.55 447.95,4288.61 499.95,4340.61 499.95,4455.81 745.23,4701.09 1262.24,4701.09 1374.56,4588.77 1403.92,4588.77 1430.71,4561.98 1476.31,4516.38 1476.31,4461.86 1468.03,4453.58 1468.03,4431.38 1506.31,4393.09 1506.31,4331.62 1494.76,4320.07 1494.76,4277.4 1491.44,4274.08 v1(1491.44,4265.92) ; v3(301,2083.04) 301.31,2083.09 301.81,2082.59 293.31,2074.09 293.31,1892.09 v1(316.31,1869.09)
  Inner Layer 4 w4: v3(103.9,2122.18) 103.9,2174.37 84.31,2193.96 84.31,2300.09 138.31,2354.09 138.31,2447.09 187.52,2496.3 187.52,2754.88 v3(127.31,2815.09)
  Inner Layer 5 w4: v3(103.9,2122.18) 102.06,2120.34 139.31,2083.09 301,2083.09 v3(301,2083.04)
GPS_ANT: R5007.1 U5004.3 | length 42.1
  Top w10: U5004.3@864.86,4527.86 885.58,4527.86 892.95,4520.49 R5007.1@892.95,4509.49
GPS_AVDD18: C5009.2 SH5001.1 U5001.40 | length 118.9
  Top w8: C5009.2@874.08,4424.11 890.71,4440.74 890.71,4461.49 901.71,4472.49 936.9,4472.49 U5001.40@938.22,4471.17
  Top w12: SH5001.1@852.23,4424.26 852.23,4424.11 C5009.2@874.08,4424.11
GPS_RF_LNA: C5004.2 U5003.1 | length 28.3
  Top w10: C5004.2@688.08,4547.11 688.08,4530.11 U5003.1@696.08,4522.11
GPS_RX_IN: U1001.D30 U5001.13 | length 178
  Top w3: U5001.13@969.71,4279.05 969.71,4267.49 974.08,4263.12 974.08,4241.11 1000.08,4215.11 1000.08,4186.26 1029.97,4156.37 U1001.D30@1029.98,4125.96
GPS_RX_IP: U1001.E30 U5001.14 | length 181.7
  Top w3: U5001.14@985.46,4279.05 985.46,4267.49 981.08,4263.11 981.08,4243.11 1006.08,4218.11 1006.08,4188.74 1036.08,4158.74 1036.08,4135.6 U1001.E30@1045.72,4125.96
GPS_RX_QN: U1001.C31 U5001.11 | length 168.8
  Top w3: U5001.11@938.22,4279.05 939.08,4278.18 939.08,4268.11 944.08,4263.11 944.08,4243.49 967.08,4220.49 967.08,4196.4 1014.23,4149.25 U1001.C31@1014.23,4141.71
GPS_RX_QP: U1001.C30 U5001.12 | length 189.1
  Top w3: U5001.12@953.96,4279.05 953.96,4266.49 950.08,4262.6 950.08,4246.49 973.08,4223.49 973.08,4199.11 1023.65,4148.54 1023.65,4135.38 U1001.C30@1014.23,4125.96
HOMEKEY: R6508.1 U2001.N6 | length 1920.6
  Top w4: v1(246.95,4405.83) 246.95,4406.68 254.36,4414.09 254.36,4434.04 254.31,4434.09 R6508.1@254.31,4463.09 ; v1(471.8,3653.09) 471.8,3635.41 625.31,3481.9 625.31,3418.09 663.57,3379.83 695.22,3379.83 v1(707.68,3367.37)
  Inner Layer 2 w3: 821.31,3195.09 822.31,3194.09 847.83,3194.09 861.83,3180.09 877.31,3180.09 877.42,3180.2 v4(884.09,3180.2)
  Inner Layer 2 w4: v3(149.31,4267.83) 149.31,4268.83 155.95,4268.83 253.31,4366.19 253.31,4399.47 v1(246.95,4405.83) ; v1(471.8,3653.09) 474.8,3656.09 494.98,3656.09 502.8,3663.91 v3(515.6,3663.91) ; v1(707.68,3367.37) 732.96,3342.09 734.28,3342.09 776.31,3300.06 776.31,3236.78 780,3233.09 780,3217.03 801.94,3195.09 821.31,3195.09
  Inner Layer 5 w4: v3(149.31,4267.83) 136.31,4254.83 136.31,3781.88 v2(187.8,3730.39) ; v2(485.31,3685.09) 497.05,3673.35 506.15,3673.35 v3(515.6,3663.91)
  Bottom w4: v2(187.8,3730.39) 187.8,3726.29 213,3701.09 469.31,3701.09 v2(485.31,3685.09)
HP_MIC: BEAD6001.1 C6020.1 C6021.2 R6011.1 R6028.2 R6030.2 | length 868.8
  Top w4: v1(920.95,2861.49) 926.95,2861.49 926.95,2859.49 R6028.2@927.95,2859.49
  Inner Layer 2 w4: v3(403.3,2782.09) 414.85,2793.64 417.86,2793.64 445.05,2820.83 581.82,2820.83 598.08,2837.09 704.66,2837.09 724.66,2857.09 908.18,2857.09 912.58,2861.49 v1(920.95,2861.49)
  Inner Layer 5 w4: v2(325.31,2776.09) 341.31,2776.09 347.31,2782.09 v3(403.3,2782.09)
  Bottom w4: BEAD6001.1@161.95,2805.9 206.95,2805.9 206.95,2804.77 208.67,2806.49 C6021.2@236.95,2806.49 237.95,2805.49 C6020.1@237.95,2784.49 237.95,2771.49 247.95,2761.49 318.91,2761.49 R6030.2@324.31,2756.09 ; R6011.1@322.67,2776.43 323.97,2776.43 R6011.1@324.31,2776.09 ; R6030.2@325.31,2756.09 R6030.2@324.31,2756.09 ; v2(325.31,2776.09) R6011.1@324.31,2776.09 ; R6030.2@324.31,2756.09 R6011.1@324.31,2776.09
HP_MP3L: BEAD6002.2 BEAD6003.1 C6008.1 R6006.1 | length 487.2
  Top w6: v1(496.95,2930.83) 496.21,2930.09 496.21,2924.47 519.44,2901.24 BEAD6002.2@519.95,2901.24
  Inner Layer 2 w4: v3(479.98,2931.08) 479.72,2930.83 v1(496.95,2930.83)
  Inner Layer 5 w5: v2(468.95,3211.83) 487.45,3193.33 487.45,2938.56 v3(479.98,2931.08)
  Bottom w4: BEAD6003.1@431.95,3256.08 BEAD6003.1@438.95,3249.08 ; BEAD6003.1@443.95,3244.49 439.36,3249.08 BEAD6003.1@438.95,3249.08 ; C6008.1@473.81,3287.49 R6006.1@451.31,3287.49 443.14,3287.49 438.95,3283.3 BEAD6003.1@438.95,3249.08
  Bottom w6: BEAD6003.1@439.36,3249.08 440.95,3249.08 468.95,3221.08 v2(468.95,3211.83)
HP_MP3R: BEAD6004.2 BEAD6005.1 C6007.1 R6007.1 | length 607.7
  Inner Layer 2 w4: v3(526.95,2885.83) 543.65,2885.83 553.65,2875.83 v1(567.36,2875.83)
  Inner Layer 5 w6: v2(404.95,3253.28) 457.2,3253.28 505.95,3204.53 505.95,2906.83 v3(526.95,2885.83)
  Bottom w4: C6007.1@333.31,3285.65 R6007.1@358.31,3285.65 374.49,3285.65 385.81,3274.32 385.81,3253.28 BEAD6005.1@388.95,3253.28 ; v2(404.95,3253.28) BEAD6005.1@392.95,3253.28 ; BEAD6005.1@388.95,3249.08 BEAD6005.1@388.95,3249.52 ; BEAD6005.1@388.95,3249.08 BEAD6005.1@389.94,3250.12 ; BEAD6005.1@388.95,3249.08 389.99,3250.12 392.95,3253.08 BEAD6005.1@392.95,3253.28 ; BEAD6005.1@388.95,3249.52 BEAD6005.1@388.95,3253.28 ; BEAD6005.1@388.95,3249.52 389.55,3250.12 BEAD6005.1@389.94,3250.12 ; BEAD6005.1@388.95,3253.28 BEAD6005.1@392.95,3253.28 ; BEAD6005.1@389.94,3250.12 BEAD6005.1@392.95,3253.28
INT_SIM1: CON6501.10 U1001.AH26 | length 5098.3
  Inner Layer 2 w3: v4(1407.93,4062.97) 1418.79,4052.11 1430.08,4052.11 1440.46,4062.49 1449.91,4062.49 1460.51,4073.09
  Inner Layer 2 w4: v3(91.31,3898.09) 141.53,3948.3 141.53,3990.91 127.79,4004.65 127.79,4019.93 136.31,4028.45 136.31,4087.73 80.95,4143.09 80.95,4246.09 159.31,4324.45 v3(159.31,4422.09) ; v3(1441.38,4820.1) 1442.53,4821.26 1618.31,4645.48 1618.31,4637.36 1626.09,4629.58 v3(1625.31,4628.8) ; 1460.51,4073.09 1463.31,4075.89 1463.31,4126.09 v3(1461.31,4128.09)
  Inner Layer 4 w4: v3(91.31,3898.09) 127.32,3862.08 127.32,3769.09 114.31,3756.08 114.31,3443.15 157.1,3400.36 157.1,3303.65 130.31,3276.86 130.31,3170.51 195.52,3105.3 195.52,2492.3 146.31,2443.09 146.31,2349.62 92.31,2295.62 92.31,2199.15 118.9,2172.56 118.9,2026.68 v3(105.31,2013.09) ; v3(159.31,4422.09) 170.2,4432.98 170.2,4434.23 288.06,4552.09 458.19,4552.09 673.19,4767.09 1388.36,4767.09 v3(1441.38,4820.1) ; v3(1461.31,4128.09) 1454.31,4135.09 1454.31,4232.13 1584.31,4362.13 1584.31,4587.8 v3(1625.31,4628.8)
  Inner Layer 5 w4: v2(87.31,1997.09) 103.05,2012.83 105.05,2012.83 v3(105.31,2013.09)
  Bottom w4: v2(87.31,1997.09) 115.3,1997.09 CON6501.10@115.3,1996.66
INT_SIM2: CON6502.10 U1001.AG26 | length 5397.6
  Top w4: v4(1392.18,4062.97) 1392.3,4062.97 1392.3,4062.85 v4(1392.18,4062.97)
  Inner Layer 2 w4: v3(178.95,1525.09) 178.95,1540.45 171.31,1548.09 171.31,1628.29 142.51,1657.09 142.51,1882.89 120.31,1905.09 120.31,2177.25 91.31,2206.25 91.31,2312.09 114.31,2335.09 114.31,2483.03 162.86,2531.58 162.86,2727.3 112.31,2777.85 112.31,2892.03 191.35,2971.07 191.35,3137.76 185.24,3143.87 185.24,3389.32 137.31,3437.25 137.31,3699.58 190.31,3752.58 190.31,4149.67 330.47,4289.83 357.26,4289.83 434.95,4367.52 434.95,4481.32 718.73,4765.09 1356.22,4765.09 1371.31,4750 1371.31,4749.32 1386.54,4734.09 1387.87,4734.09 1439.31,4682.65 1439.31,4667.25 1488.95,4617.62 1498.83,4617.62 v3(1536.1,4580.34) ; v3(1354.31,4026.09) 1374.17,4045.94 1375.15,4045.94 v4(1392.18,4062.97)
  Inner Layer 4 w4: v3(1354.31,4026.09) 1397.95,4069.72 1397.95,4232.49 1520.95,4355.49 1520.95,4572.09 1529.2,4580.34 v3(1536.1,4580.34)
  Inner Layer 5 w4: v2(113.31,1386.09) 113.31,1459.45 v3(178.95,1525.09)
  Bottom w4: v2(113.31,1386.09) 113.31,1386.18 CON6502.10@113.14,1386.35 ; CON6502.10@113.14,1386.35 112.41,1387.09 CON6502.10@113.14,1386.35
IR_GPIO: Q6301.1 R6351.2 U1001.J28 | length 1567.8
  Top w4: R6351.2@558.95,4675.99 558.95,4697.62 Q6301.1@578.2,4716.87 ; Q6301.1@578.2,4717.85 Q6301.1@578.2,4716.87 ; U1001.J28@1108.72,4094.47 1108.71,4073.72 v4(1120.95,4061.49) ; v1(1207.33,4499.65) 1207.33,4690.1 1199.48,4697.96 597.11,4697.96 Q6301.1@578.2,4716.87
  Inner Layer 2 w4: v4(1120.95,4061.49) 1126.31,4056.12 v3(1126.31,4047.09) ; v3(1183.88,4545.09) 1183.88,4529.87 1207.33,4506.42 v1(1207.33,4499.65) 1195.31,4487.63 1195.31,4413.38 v3(1202.63,4406.06)
  Inner Layer 5 w4: v3(1126.31,4047.09) 1135.31,4038.09 1135.31,4035.43 1135.66,4035.43 v2(1135.78,4034.77) ; v2(1191.31,4370.09) 1191.31,4394.74 v3(1202.63,4406.06)
  Bottom w4: v2(1135.78,4034.77) 1110.64,4034.77 1089.31,4056.09 1089.31,4159.09 1098.31,4168.09 1098.31,4289.51 1178.89,4370.09 v2(1191.31,4370.09)
ISENSE: R2044.1 R2135.1 U2106.1 U2106.2 U2106.5 U2106.6 | length 276.5
  Bottom w4: R2044.1@875.95,3359.49 875.95,3361.49 879.95,3365.49 879.95,3404.94 R2135.1@890.71,3415.7
  Bottom w20: U2106.2@543.31,3632.88 U2106.5@543.31,3731.3 ; U2106.1@580.71,3632.88 U2106.6@580.71,3731.3 ; R2135.1@890.71,3415.7 R2135.1@894.5,3419.49 R2135.1@894.5,3431.49
JTCK: CON9001.27 U1001.AJ30 | length 4550.1
  Top w3: U1001.AJ30@1423.68,4125.96 1435.82,4138.11 1435.82,4153.85
  Top w4: 1435.82,4153.85 1464.22,4182.25 v1(1470.76,4182.25)
  Inner Layer 2 w4: v3(216.31,3258.98) 222.91,3265.58 222.91,3478.33 245.31,3500.73 245.31,3653.91 224.31,3674.91 224.31,4030.68 243.31,4049.68 243.31,4079.9 261.95,4098.54 261.95,4176.06 339.72,4253.83 366.51,4253.83 467.31,4354.63 467.31,4468.42 731.98,4733.09 1275.61,4733.09 1386.61,4622.09 1415.85,4622.09 1508.31,4529.63 1508.31,4471.79 1546.31,4433.79 1546.31,4309.79 1536.31,4299.79 1536.31,4239.72 1506.47,4209.88 1478.85,4182.25 v1(1470.76,4182.25)
  Inner Layer 4 w4: v3(216.31,3258.98) 228.32,3258.98 306.31,3181 306.31,2794.77 232.31,2720.77 232.31,2480.52 209.95,2458.16 209.95,2425.57 v3(221.4,2414.12)
  Inner Layer 5 w4: v3(221.4,2414.12) 264.11,2456.83 349.78,2456.83 399.31,2407.3 399.31,2345.09 v2(416.31,2328.09) ; v2(499.9,2329.81) 502.92,2332.83 578.29,2332.83 v2(583.95,2338.49)
  Bottom w4: v2(416.31,2328.09) 417.31,2329.09 499.9,2329.09 v2(499.9,2329.81) ; v2(583.95,2338.49) 607.43,2361.97 CON9001.27@655.53,2361.97
JTDI: CON9001.23 U1001.AJ29 | length 4381.3
  Top w4: v4(1423.68,4110.21) 1423.31,4110.09 1423.31,4109.85 v4(1423.68,4110.21) ; v4(1423.68,4110.21) 1422.44,4110.21 v4(1423.68,4110.21)
  Inner Layer 2 w4: v3(212.48,3149.71) 201.31,3160.87 201.31,3267.93 214.37,3280.98 214.37,3481.7 237.31,3504.64 237.31,3643.85 216.31,3664.85 216.31,4035.7 234.31,4053.7 234.31,4084.93 251.95,4102.57 251.95,4177.37 337.41,4262.83 364.2,4262.83 458.95,4357.58 458.95,4471.37 728.67,4741.09 1278.95,4741.09 1387.95,4632.09 1402.31,4632.09 1402.43,4632.21 1417.05,4632.21 1516.31,4532.94 1516.31,4475.87 1554.31,4437.87 1554.31,4305.57 1544.31,4295.57 1544.31,4236.3 1478.1,4170.09 1446.64,4170.09 1416.31,4139.77 1416.31,4117.57 v4(1423.68,4110.21)
  Inner Layer 5 w4: v3(212.48,3149.71) 220.95,3147.83 223.79,3147.83 297.63,3073.98 297.63,3009.45 171.31,2883.13 171.31,2779.09 260.31,2690.09 260.31,2660.94 382.31,2538.94 382.31,2522.09 v2(403.31,2501.09) ; v2(493.15,2418.84) 524.62,2387.38 v2(583.82,2387.38)
  Bottom w4: v2(403.31,2501.09) 485.56,2418.84 v2(493.15,2418.84) ; v2(583.82,2387.38) 589.9,2393.46 592.97,2393.46 CON9001.23@655.53,2393.47
JTDO: CON9001.19 U1001.AK28 | length 4596.4
  Top w3: U1001.AK28@1439.43,4094.47 1461.33,4094.46 1478.31,4111.45 1486.31,4119.45 1486.31,4137.09
  Top w4: U1001.AK28@1439.43,4094.47 1439.42,4094.9 U1001.AK28@1439.43,4094.47 ; 1486.31,4137.09 1486.31,4152.36 1496.8,4162.85 1501.47,4162.85 v1(1510.26,4171.64)
  Inner Layer 2 w4: v3(162.95,3218.61) 177.21,3232.87 177.21,3386.03 129.31,3433.93 129.31,3705.65 182.12,3758.45 182.12,4152.79 328.82,4299.49 355.6,4299.49 425.49,4369.38 425.49,4483.17 715.41,4773.09 1434.1,4773.09 1578.31,4628.88 1578.31,4293.52 1568.31,4283.52 1568.31,4214.48 1525.48,4171.64 v1(1510.26,4171.64)
  Inner Layer 5 w4: v3(162.95,3218.61) 175.8,3218.61 202.31,3192.09 223.76,3192.09 247.76,3168.09 265.91,3168.09 322.31,3111.68 322.31,3000.19 195.31,2873.19 195.31,2789.03 284.31,2700.03 284.31,2672.06 429.84,2526.53 v2(429.84,2514.95) ; v2(493.93,2471.4) 493.93,2466.03 536.87,2423.09 v2(583.95,2423.09)
  Bottom w4: v2(429.84,2514.95) 473.4,2471.4 v2(493.93,2471.4) ; v2(583.95,2423.09) 585.83,2424.96 CON9001.19@655.53,2424.96
JTMS: CON9001.21 U1001.AJ31 | length 4265.5
  Top w4: U1001.AJ31@1423.68,4141.71 1423.67,4153.01 1469.89,4199.23 1479.12,4199.23 v1(1479.12,4199.49)
  Inner Layer 2 w4: v3(217.71,3172.14) 218.68,3173.11 209.31,3182.47 209.31,3227.59 231.31,3249.59 231.31,3474.82 279.31,3522.82 279.31,3950.93 241.31,3988.93 241.31,4034.67 251.84,4045.19 251.84,4074.39 272.02,4094.57 272.02,4174.81 343.04,4245.83 369.83,4245.83 475.31,4351.32 475.31,4465.11 735.3,4725.09 1272.28,4725.09 1383.28,4614.09 1412.54,4614.09 1500.31,4526.31 1500.31,4467.72 1538.31,4429.72 1538.31,4314.01 1528.31,4304.01 1528.31,4243.14 1484.66,4199.49 v1(1479.12,4199.49) v1@1481.62,4199.23
  Inner Layer 5 w4: v3(217.71,3172.14) 221.95,3169.83 237.84,3153.94 237.84,3149.41 306.31,3080.94 306.31,3006.82 179.31,2879.82 179.31,2782.4 268.31,2693.4 268.31,2664.64 394.31,2538.64 394.31,2526.96 407.19,2514.09 407.31,2514.09 v2(419.31,2502.09) ; v2(493.74,2446.75) 525.41,2415.09 572.15,2415.09 581.11,2406.13 v2(584.31,2406.13)
  Bottom w4: v2(419.31,2502.09) 474.65,2446.75 v2(493.74,2446.75) ; v2(584.31,2406.13) 587.4,2409.22 CON9001.21@655.53,2409.22
KPCOL0: CON6504.2 CON9001.6 U1001.AL24 | length 5004.1
  Top w4: CON6504.2@147.48,3992.02 147.48,4008.48 152.83,4013.83 v1(153.53,4013.83) ; U1001.AL24@1455.17,4031.47 1492.79,4031.47 1550.31,4089 1550.31,4162.07 1580.31,4192.07 v1(1580.31,4230.09)
  Inner Layer 2 w4: v3(123.3,3396.11) 113.31,3406.1 113.31,3670.45 84.31,3699.45 84.31,3717.58 157.53,3790.8 157.53,4009.83 v1(153.53,4013.83) 153.31,4013.8 153.31,4093.6 96.95,4149.96 96.95,4229.36 116.69,4249.09 152.42,4249.09 272.31,4368.98 272.31,4556.41 344.99,4629.09 434.94,4629.09 636.95,4831.1 v3(636.95,4882.49) ; v3(1272.95,4906.83) 1272.95,4893.09 1360.95,4805.09 1447.36,4805.09 1610.31,4642.13 1610.31,4258.12 1581.3,4229.1 v1(1580.31,4230.09)
  Inner Layer 4 w4: v3(636.95,4882.49) 637.95,4883.49 646.95,4883.49
  Inner Layer 5 w4: v3(123.3,3396.11) 138.31,3381.1 138.31,3157.13 206.31,3089.13 206.31,2968.6 104.31,2866.6 104.31,2748.87 281.3,2571.89 v2(322.86,2571.89) ; v3(636.95,4882.49) 645.61,4873.83 1256.51,4873.83 1272.95,4890.27 v3(1272.95,4906.83)
  Bottom w4: v2(322.86,2571.89) 346.06,2595.09 416.31,2595.09 424.31,2603.09 424.31,2603.58 427.83,2607.09 449.74,2607.09 521.63,2535.2 CON9001.6@559.07,2535.2
KPCOL1: R6509.1 U1001.AK24 | length 2484
  Top w3: U1001.AK24@1439.43,4031.47 1445.84,4037.89 1445.95,4037.89 1446.95,4038.89 1446.95,4039 1449.04,4041.09 1491.08,4041.09 1499.26,4049.27
  Top w4: v1(284.95,4443.4) 294.31,4452.77 R6509.1@294.31,4483.09 ; 1499.26,4049.27 1542.31,4092.32 1542.31,4173.86 1567.23,4198.78 1567.23,4234.69 1579.97,4247.43 v1(1581.31,4246.09)
  Inner Layer 2 w4: v1(284.95,4443.4) 284.95,4557.74 344.7,4617.49 434.81,4617.49 644.95,4827.63 644.95,4865.09 653.95,4874.09 v3(653.95,4909.49) ; v3(1250.95,4889.49) 1264.77,4889.49 1357.17,4797.09 1444.04,4797.09 1602.31,4638.82 1602.31,4267.09 v1(1581.31,4246.09)
  Inner Layer 5 w4: v3(653.95,4909.49) 681.31,4882.13 1240.35,4882.13 1247.71,4889.49 v3(1250.95,4889.49)
KPROW0: CON6504.1 CON9001.8 U1001.AH23 | length 5084
  Top w4: v1(138.5,3856.64) 138.5,3858.16 CON6504.1@147.48,3858.16
  Inner Layer 2 w4: v3(119.54,3372.17) 104.95,3386.76 104.95,3665.07 76.31,3693.71 76.31,3729.83 138.47,3791.99 v1(138.5,3856.64) ; v1(138.5,3856.64) 149.53,3867.7 149.53,3994.23 141.53,4002.23 141.53,4018.73 144.31,4021.52 144.31,4091.04 88.95,4146.4 88.95,4235 128.61,4274.66 133.14,4274.66 v3(149.31,4290.83) ; v4(1407.93,4015.73) 1436.39,4015.73 1487.32,4066.66 1487.32,4106.3 1626.31,4245.29 1626.31,4595.99 1648.31,4617.99 1648.31,4645.96 1458.31,4835.96 v3(1458.31,4871.22)
  Inner Layer 4 w4: v3(149.31,4290.83) 149.31,4356.35 144.31,4361.35 144.31,4428.3 276.6,4560.59 455.38,4560.59 669.88,4775.09 1329.63,4775.09 1425.76,4871.22 v3(1458.31,4871.22)
  Inner Layer 5 w4: v3(119.54,3372.17) 130.31,3361.4 130.31,3151.19 198.31,3083.19 198.31,2972.12 96.31,2870.12 96.31,2734.18 216.36,2614.13 219.65,2614.13 v2(219.65,2611.53)
  Bottom w4: v2(219.65,2611.53) v2@222.5,2614.13 ; 224.31,2617.09 v2@222.5,2614.13 ; v2@222.5,2614.13 229.31,2622.09 245.31,2638.09 452.81,2638.09 510.81,2580.09 573.46,2580.09 579.84,2573.71 579.84,2528.19 571.1,2519.45 CON9001.8@561.95,2519.45 ; CON9001.8@561.95,2519.45 561.95,2518.49 CON9001.8@559.07,2519.45 CON9001.8@561.95,2519.45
